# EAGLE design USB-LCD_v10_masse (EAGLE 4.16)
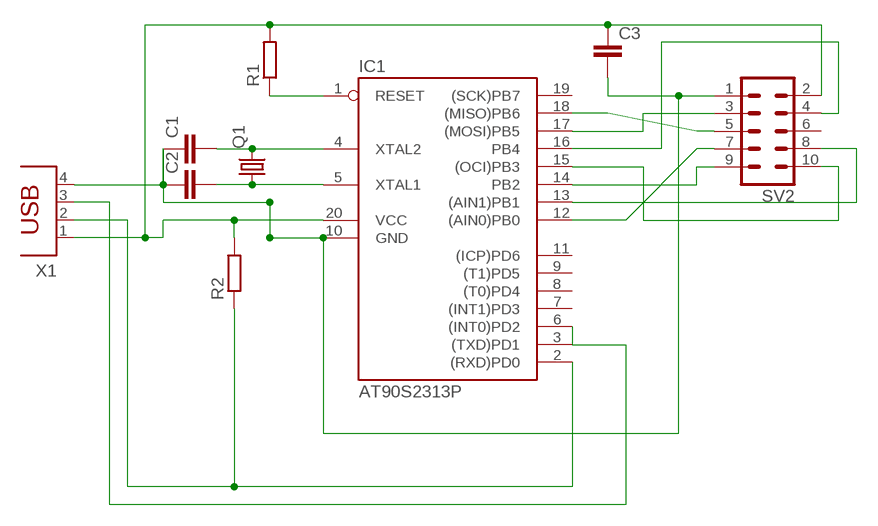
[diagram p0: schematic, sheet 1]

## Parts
C1  C2,5-3  [C2.5-3]
C2  C2,5-3  [C2.5-3]
C3  C2.5/6  [C2.5-6]
IC1  AT90S2313P  [DIL20]
Q1  CRYSTALHC49S  [HC49/S]
R1  R-EU_0207/10  [0207/10]
R2  R-EU_0207/10  [0207/10]
SV2  ML10  [ML10]
X1  PN61729  [PN61729]

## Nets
N$1: IC1.3((TXD)PD1) IC1.6((INT0)PD2) X1.3
N$2: IC1.2((RXD)PD0) R2.1 X1.2
N$3: IC1.16(PB4) SV2.4
N$4: C1.1 C2.1 C3.2 IC1.10(GND) SV2.1 X1.4
N$5: C1.2 IC1.4(XTAL2) Q1.2
N$6: C2.2 IC1.5(XTAL1) Q1.1
N$7: C3.1 IC1.20(VCC) R1.2 R2.2 SV2.2 X1.1
N$8: IC1.17((MOSI)PB5) SV2.3
N$9: IC1.18((MISO)PB6) SV2.5
N$10: IC1.13((AIN1)PB1) SV2.8
N$11: IC1.12((AIN0)PB0) SV2.7
N$12: IC1.14(PB2) SV2.9
N$13: IC1.15((OCI)PB3) SV2.10
N$16: IC1.1(RESET) R1.1
Unconnected: IC1.7((INT1)PD3) IC1.8((T0)PD4) IC1.9((T1)PD5) IC1.11((ICP)PD6) IC1.19((SCK)PB7) SV2.6

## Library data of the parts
C1-C3 = capacitor-wima:C: CAPACITOR
IC1 = atmel:AT90S2313: MICROCONTROLLER 2 Kbytes FLASH 128 bytes SRAM 128 bytes EEPROM UART
Q1 = crystal:CRYSTAL: CRYSTAL
R1 R2 = rcl:R-EU_: RESISTOR, European symbol
SV2 = con-harting-ml:ML10: HARTING
X1 = con-berg:PN61729: BERG USB connector

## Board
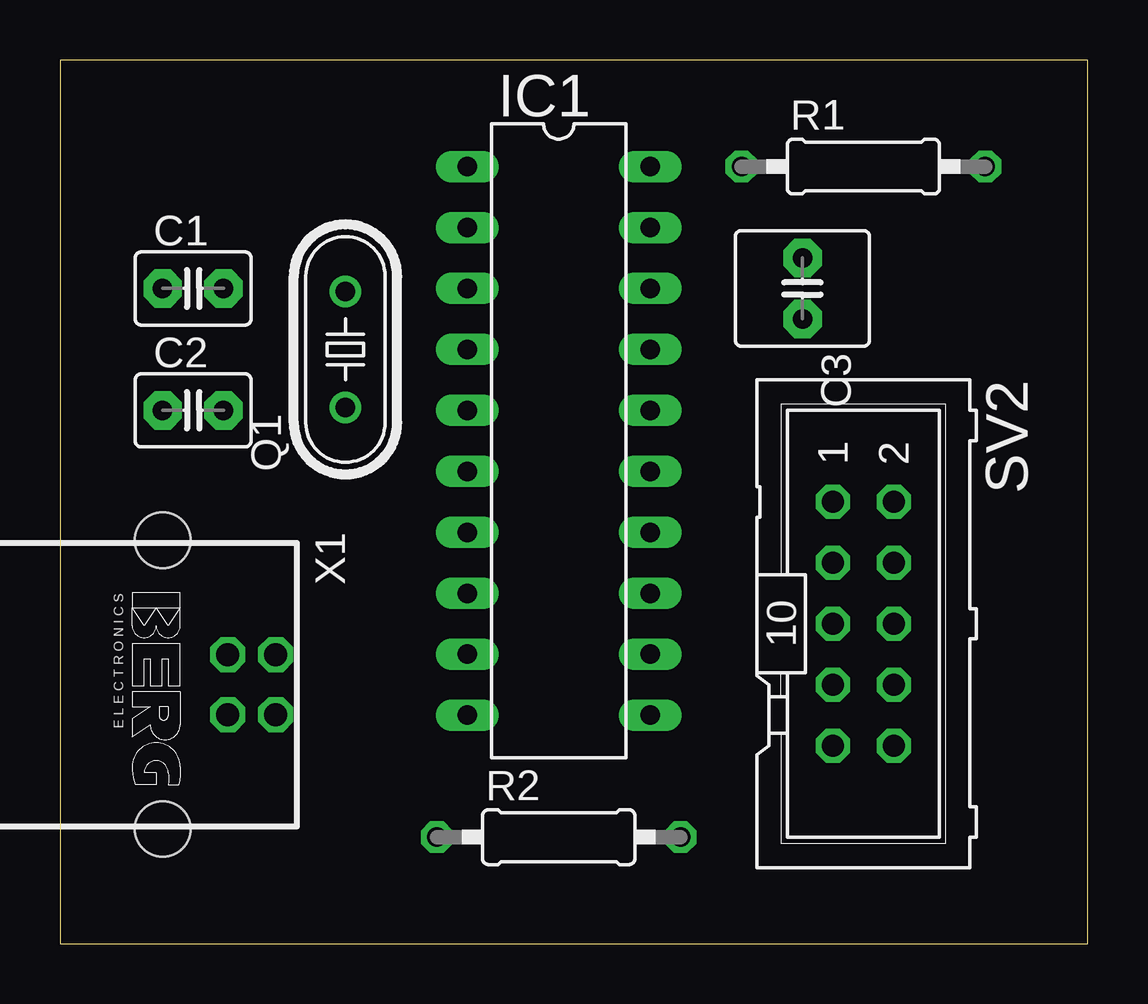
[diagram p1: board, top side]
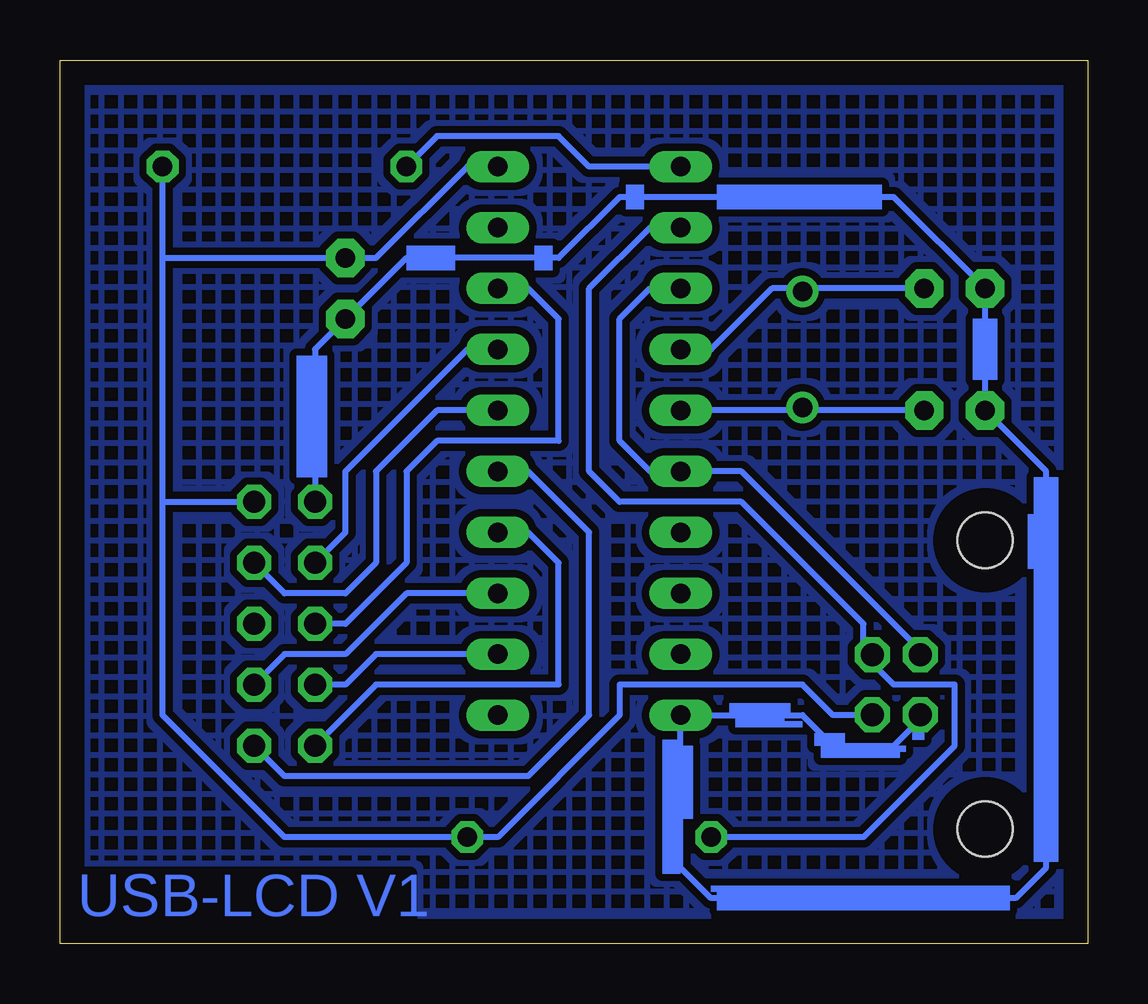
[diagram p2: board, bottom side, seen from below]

Size 42.85 x 36.82 mm. Coordinates in mm from the lower left corner, seen from the top.
Outline: 0,0 42.85,0 42.85,36.82 0,36.82 0,0
Copper layers (1*16): Top 0.035mm / dielectric 1.5mm / Bottom 0.035mm
Design rules "default": minimum track width 10mil, minimum drill 24mil, track to track 8mil, track to pad 8mil, pad to pad 8mil, via to via 8mil, smd to smd 8mil, copper to edge 40mil, drill to drill 8mil, minimum pad ring 10mil, minimum via ring 8mil, stop-mask expansion 4mil, vias tented up to drill 0mil, thermal gap 10mil

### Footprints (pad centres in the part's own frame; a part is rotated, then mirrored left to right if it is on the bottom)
C2.5-3 = drill 0.813 pad 1.6 octagon: 1 -1.27,0; 2 1.27,0
C2.5-6 = drill 0.813 pad 1.6 octagon: 1 -1.27,0; 2 1.27,0
DIL20 = drill 0.813 long: 1 -11.43,-3.81; 2 -8.89,-3.81; 3 -6.35,-3.81; 4 -3.81,-3.81; 5 -1.27,-3.81; 6 1.27,-3.81; 7 3.81,-3.81; 8 6.35,-3.81; 9 8.89,-3.81; 10 11.43,-3.81; 11 11.43,3.81; 12 8.89,3.81; 13 6.35,3.81; 14 3.81,3.81; 15 1.27,3.81; 16 -1.27,3.81; 17 -3.81,3.81; 18 -6.35,3.81; 19 -8.89,3.81; 20 -11.43,3.81
HC49/S = drill 0.813 round: 1 -2.413,0; 2 2.413,0
0207/10 = drill 0.813 octagon: 1 -5.08,0; 2 5.08,0
ML10 = drill 0.914 octagon: 1 -5.08,-1.27; 2 -5.08,1.27; 3 -2.54,-1.27; 4 -2.54,1.27; 5 0,-1.27; 6 0,1.27; 7 2.54,-1.27; 8 2.54,1.27; 9 5.08,-1.27; 10 5.08,1.27
PN61729 = drill 0.95 octagon: 1 1.25,4.71; 2 -1.25,4.71; 3 -1.25,2.71; 4 1.25,2.71 | hole 2.3: -6.02,0; 6.02,0

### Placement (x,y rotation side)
C1  5.55,27.3 0 top
C2  5.55,22.22 0 top
C3  30.95,27.3 270 top
IC1  20.79,20.95 270 top
Q1  11.9,24.76 90 top
R1  33.49,32.38 0 top
R2  20.79,4.44 0 top
SV2  33.49,13.33 270 top
X1  4.28,10.79 270 top

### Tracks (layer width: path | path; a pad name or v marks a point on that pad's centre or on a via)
N$1
  Bottom 0.254: X1.3 6.82,12.06 14.44,19.68 IC1.6 18.25,19.68 19.52,20.95 19.52,26.03 18.25,27.3 IC1.3
N$2
  Bottom 0.254: R2.1 9.36,4.44 5.55,8.25 5.55,10.79 8.09,10.79 9.36,12.06 | 9.36,12.06 9.36,13.33 14.44,18.41 19.52,18.41 20.79,19.68 20.79,27.3 18.25,29.84 IC1.2 | 9.36,12.06 X1.2
N$3
  Bottom 0.254: SV2.4 33.49,14.6 30.95,14.6 29.68,15.87 29.68,19.68 27.14,22.22 IC1.16
N$4
  Bottom 0.254: X1.4 6.82,9.52 8.09,8.25 10.63,8.25 11.9,9.52 IC1.10 16.98,3.17 15.71,1.9 3.01,1.9 1.74,3.17 1.74,19.68 C2.1 C1.1 8.09,31.11 19.52,31.11 22.06,28.57 28.41,28.57 C3.2 32.22,24.76 SV2.1
N$5
  Bottom 0.254: C1.2 11.9,27.3 | 11.9,27.3 13.17,27.3 15.71,24.76 IC1.4 | 11.9,27.3 Q1.2
N$6
  Bottom 0.254: 11.9,22.22 IC1.5 | C2.2 11.9,22.22 | 11.9,22.22 Q1.1
N$7
  Bottom 0.254: IC1.20 25.87,32.38 29.68,28.57 C3.1 38.57,28.57 | 38.57,28.57 R1.2 | 38.57,18.41 38.57,28.57 | 38.57,18.41 38.57,9.52 33.49,4.44 R2.2 24.6,4.44 19.52,9.52 19.52,10.79 11.9,10.79 10.63,9.52 9.36,9.52 X1.1 | 38.57,18.41 SV2.2
N$8
  Bottom 0.254: SV2.3 30.95,17.14 30.95,19.68 25.87,24.76 IC1.17
N$9
  Bottom 0.254: SV2.5 30.95,13.33 28.41,15.87 28.41,19.68 27.14,20.95 22.06,20.95 22.06,26.03 23.33,27.3 IC1.18
N$10
  Bottom 0.254: SV2.8 33.49,12.06 30.95,12.06 28.41,14.6 IC1.13
N$11
  Bottom 0.254: SV2.7 30.95,10.79 29.68,12.06 IC1.12
N$12
  Bottom 0.254: SV2.9 29.68,10.79 22.06,10.79 22.06,15.87 23.33,17.14 IC1.14
N$13
  Bottom 0.254: SV2.10 33.49,6.98 23.33,6.98 20.79,9.52 20.79,17.14 23.33,19.68 IC1.15
N$14
  pour Bottom (isolate 0.305, hatched): 0.47,36.19 42.38,36.19 42.38,0.63 0.47,0.63
N$16
  Bottom 0.254: R1.1 27.14,33.65 22.06,33.65 20.79,32.38 IC1.1
(copper drawn outside any net)
  shapes: Bottom area x21

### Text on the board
Bottom: USB-LCD V1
